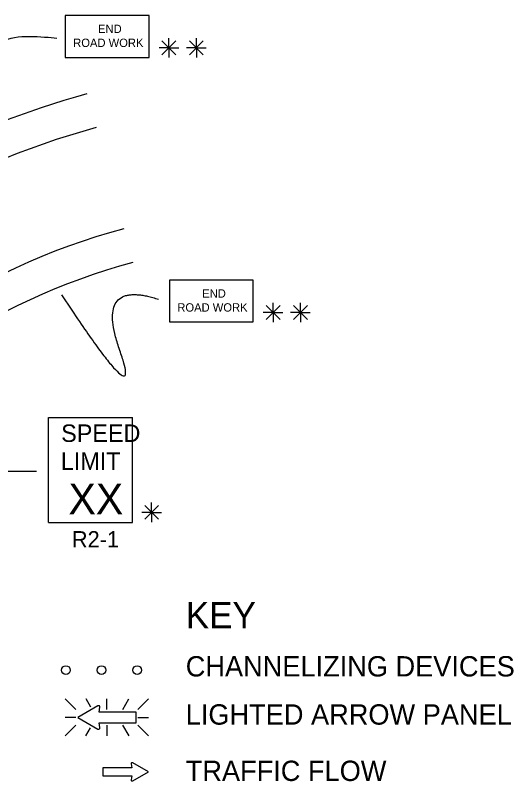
# Model space of a CAD drawing. Extents: x 16728 to 19508, y 5553 to 7079.
# Drawn here: x 17179.3 to 17407.4, y 6484.5 to 6837.7 of the extents above; entities that cross this region are included whole.
import ezdxf

# ---------------------------------------------------------------- set-up
doc = ezdxf.new("R2010")
doc.units = 0
for name, color, linetype in [('MT_SCRATCH_LEVEL_E', 7, 'Continuous'), ('PAVT_EDGE_EX', 7, 'Continuous'), ('TRAFFIC_SIGNS_PR', 7, 'Continuous'), ('TYPICAL_TEXT_DIMEN_EX', 7, 'Continuous'), ('TYPICAL_TEXT_DIMEN_PR', 7, 'Continuous')]:
    doc.layers.add(name, color=color, linetype=linetype)

msp = doc.modelspace()

# ---------------------------------------------------------------- linework, layer by layer
at = {"layer": 'MT_SCRATCH_LEVEL_E'}
for p, q in [((17232.32, 6494.92), (17232.64, 6493.15)), ((17240.25, 6491.29), (17233.01, 6495.4)), ((17232.64, 6493.15), (17219.38, 6493.15)), ((17219.38, 6493.15), (17219.38, 6489.4)), ((17233.01, 6487.15), (17240.25, 6491.29)), ((17219.38, 6489.4), (17232.64, 6489.4)), ((17232.64, 6489.4), (17232.32, 6487.62))]:
    msp.add_line(p, q, dxfattribs=at)
for centre, start, end in [((17232.78, 6495), 60.4248, 189.9638), ((17232.78, 6487.55), 170.0362, 299.7731)]:
    msp.add_arc(centre, 0.463, start, end, dxfattribs=at)
at = {"layer": 'PAVT_EDGE_EX'}
for radius, start, end in [(380, 105.2177, 157.5011), (364, 105.2176, 137.0843), (316, 105.2177, 180), (300, 105.2177, 180)]:
    msp.add_arc((17311.82, 6435.06), radius, start, end, dxfattribs=at)
at = {"layer": 'TRAFFIC_SIGNS_PR'}
for p, q in [((17194.5, 6653.49), (17232.9, 6653.49)), ((17194.5, 6605.49), (17194.5, 6653.49)), ((17232.9, 6605.49), (17232.9, 6653.49)), ((17194.5, 6605.49), (17232.9, 6605.49)), ((17202.1, 6524.68), (17207.03, 6519.75)), ((17213.86, 6520.86), (17211.65, 6524.69)), ((17221.18, 6519.75), (17221.18, 6524.69)), ((17228.42, 6519.75), (17231.27, 6524.69)), ((17235.33, 6519.75), (17240.27, 6524.69)), ((17207.03, 6516.2), (17202.1, 6516.2)), ((17235.33, 6516.2), (17240.27, 6516.2)), ((17202.1, 6507.71), (17207.03, 6512.64)), ((17221.18, 6512.64), (17221.18, 6507.7)), ((17231.31, 6507.7), (17228.46, 6512.64)), ((17235.33, 6512.64), (17240.27, 6507.7)), ((17211.61, 6507.7), (17213.72, 6511.37))]:
    msp.add_line(p, q, dxfattribs=at)
for points in [[(17202.15, 6818.46), (17240.55, 6818.46), (17240.55, 6837.66), (17202.15, 6837.66)], [(17249.82, 6697.28), (17288.22, 6697.28), (17288.22, 6716.48), (17249.82, 6716.48)]]:
    msp.add_lwpolyline(points, close=True, dxfattribs=at)
for points in [[(17217.11, 6521.47), (17207.82, 6516.2), (17217.11, 6510.87)], [(17217.98, 6511.5), (17217.58, 6513.77), (17234.6, 6513.77), (17234.6, 6518.57), (17217.58, 6518.57), (17217.99, 6520.85)]]:
    msp.add_lwpolyline(points, dxfattribs=at)
for centre in [(17202.44, 6537.88), (17218.74, 6537.88), (17235.04, 6537.88)]:
    msp.add_circle(centre, 2, dxfattribs=at)
for centre, radius, start, end in [((17217.4, 6520.95), 0.598, 350.7308, 118.8916), ((17217.4, 6511.4), 0.597, 241.4833, 9.9593)]:
    msp.add_arc(centre, radius, start, end, dxfattribs=at)
at = {"layer": 'TYPICAL_TEXT_DIMEN_PR'}
for p, q in [((17249.58, 6822.83), (17249.58, 6827.29)), ((17262.14, 6822.83), (17262.14, 6827.29)), ((17249.58, 6822.83), (17245.05, 6822.83)), ((17246.39, 6826.02), (17252.77, 6819.64)), ((17252.77, 6826.02), (17246.39, 6819.64)), ((17249.58, 6822.83), (17252.77, 6822.83)), ((17249.58, 6822.83), (17254.06, 6822.83)), ((17249.58, 6822.83), (17249.58, 6818.33)), ((17262.14, 6822.83), (17257.6, 6822.83)), ((17258.95, 6826.02), (17265.33, 6819.64)), ((17265.33, 6826.02), (17258.95, 6819.64)), ((17262.14, 6822.83), (17265.33, 6822.83)), ((17262.14, 6822.83), (17266.62, 6822.83)), ((17262.14, 6822.83), (17262.14, 6818.33)), ((17297.25, 6701.65), (17297.25, 6706.11)), ((17309.81, 6701.65), (17309.81, 6706.11)), ((17294.06, 6704.84), (17300.44, 6698.46)), ((17300.44, 6704.84), (17294.06, 6698.46)), ((17306.62, 6704.84), (17312.99, 6698.46)), ((17312.99, 6704.84), (17306.62, 6698.46)), ((17297.25, 6701.65), (17292.71, 6701.65)), ((17297.25, 6701.65), (17300.44, 6701.65)), ((17297.25, 6701.65), (17301.72, 6701.65)), ((17297.25, 6701.65), (17297.25, 6697.15)), ((17309.81, 6701.65), (17305.27, 6701.65)), ((17309.81, 6701.65), (17312.99, 6701.65)), ((17309.81, 6701.65), (17314.28, 6701.65)), ((17309.81, 6701.65), (17309.81, 6697.15)), ((17170.75, 6628.99), (17189.02, 6628.99)), ((17241.68, 6610.1), (17241.68, 6614.56)), ((17244.87, 6613.29), (17238.49, 6606.91)), ((17238.5, 6613.29), (17244.87, 6606.91)), ((17241.68, 6610.1), (17237.15, 6610.1)), ((17241.68, 6610.1), (17244.87, 6610.1)), ((17241.68, 6610.1), (17246.16, 6610.1)), ((17241.68, 6610.1), (17241.68, 6605.6))]:
    msp.add_line(p, q, dxfattribs=at)
for points, degree in [([(17174.09, 6792.93), (17168.08, 6812.93), (17166.4, 6831.03), (17192.21, 6827.78), (17198.29, 6827.27)], 3), ([(17200.44, 6709.72), (17238.68, 6651.54), (17215.46, 6717.25), (17244.82, 6707.66)], 2)]:
    msp.add_open_spline(points, degree=degree, dxfattribs=at)

# ---------------------------------------------------------------- texts
at = {"layer": 'TRAFFIC_SIGNS_PR'}
for s, height, p in [('END', 3.831, (17217.15, 6829.59)), ('ROAD WORK', 3.831, (17205.76, 6823.2)), ('END', 3.831, (17264.82, 6708.41)), ('ROAD WORK', 3.831, (17253.43, 6702.02)), ('SPEED', 8, (17200.26, 6642.35)), ('LIMIT', 8, (17200.1, 6629.55)), ('XX', 14.031, (17203.61, 6609.25)), ('R2-1', 7.44, (17205.17, 6594.05))]:
    msp.add_text(s, height=height, dxfattribs=at).set_placement(p)
at = {"layer": 'TYPICAL_TEXT_DIMEN_EX'}
for s, height, p in [('KEY', 12, (17257.28, 6556.99)), ('CHANNELIZING DEVICES', 9.3, (17257.28, 6534.94)), ('LIGHTED ARROW PANEL', 9.3, (17257.28, 6512.89)), ('TRAFFIC FLOW', 9.3, (17257.28, 6487.09))]:
    msp.add_text(s, height=height, dxfattribs=at).set_placement(p)

doc.saveas('drawing.dxf')
